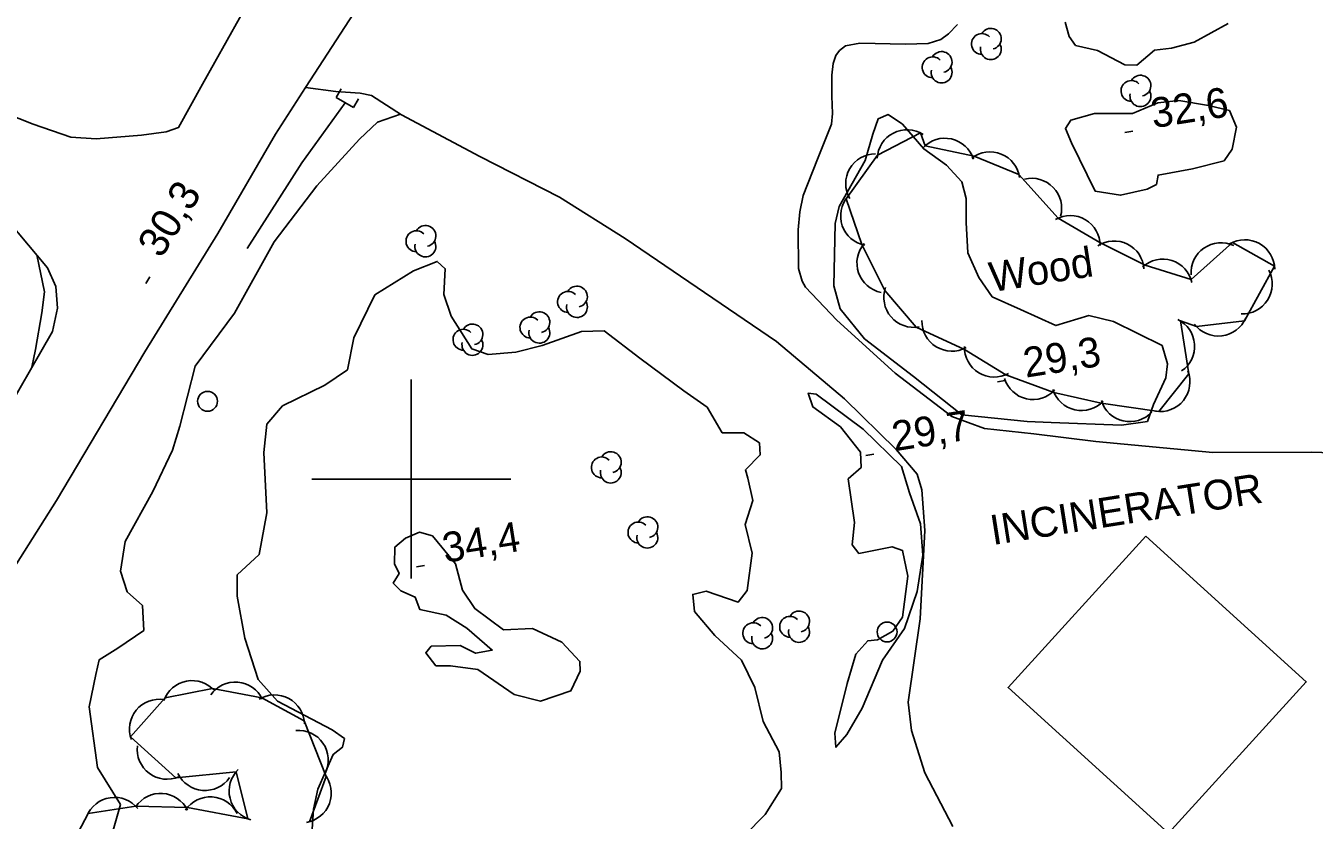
# Model space of a CAD drawing. Extents: x 646142 to 649934, y 5874075 to 5876351.
# Drawn here: x 648161.2 to 648290.8, y 5875365.7 to 5875445.6 of the extents above; entities that cross this region are included whole.
import ezdxf

# ---------------------------------------------------------------- set-up
doc = ezdxf.new("R2010")
doc.units = 0
for name, color, linetype in [('Niveau 1', 7, 'Continuous'), ('Niveau 19', 7, 'Continuous'), ('Niveau 2', 7, 'Continuous'), ('Niveau 21', 7, 'Continuous'), ('Niveau 26', 7, 'Continuous'), ('Niveau 3', 7, 'Continuous'), ('Niveau 31', 7, 'Continuous'), ('Niveau 36', 7, 'Continuous'), ('Niveau 4', 7, 'Continuous'), ('Niveau 44', 7, 'Continuous'), ('Niveau 61', 7, 'Continuous')]:
    doc.layers.add(name, color=color, linetype=linetype)

msp = doc.modelspace()

# ---------------------------------------------------------------- linework, layer by layer
at = {"layer": 'Niveau 1'}
for points in [[(648198.91, 5875436.7), (648196.61, 5875435.88), (648194.79, 5875434.19), (648190.5, 5875429.47), (648186.22, 5875423.84), (648182.23, 5875416.67), (648178.28, 5875411.35), (648176.73, 5875405.31), (648175.99, 5875402.89)], [(648261.93, 5875405.79), (648255.36, 5875406.46), (648250.49, 5875410.31), (648245.57, 5875414.11), (648243.11, 5875417.13), (648242.47, 5875419.43), (648242.63, 5875425.7), (648243.02, 5875427.4), (648245.65, 5875432.04), (648246.42, 5875434.68), (648246.94, 5875436.22), (648247.94, 5875436.64), (648249.38, 5875435.67), (648251.52, 5875433.2), (648253.82, 5875431.55), (648255.37, 5875429.89), (648255.78, 5875428.2), (648255.79, 5875425.79), (648255.96, 5875422.76), (648257.07, 5875420.27), (648258.42, 5875418.31), (648261.26, 5875417.05), (648264.81, 5875415.44), (648268.11, 5875416.45), (648270.62, 5875415.85), (648275.49, 5875413.43), (648276.03, 5875411.58), (648275.85, 5875410.19), (648274.62, 5875407.51), (648274.01, 5875405.79), (648271.41, 5875405.41), (648264.34, 5875405.7), (648261.93, 5875405.79)], [(648161.85, 5875411.24), (648162.21, 5875413.04), (648162.85, 5875416.71), (648163.14, 5875418.82), (648162.35, 5875422.53)], [(648240.72, 5875408.55), (648245.45, 5875405.02), (648249.28, 5875401.26), (648250.11, 5875398.62), (648251.2, 5875395.5), (648251.44, 5875392.36), (648250.86, 5875388.69), (648249.59, 5875384.97), (648247.37, 5875381.8), (648245.32, 5875376.98), (648243.81, 5875374.33), (648242.7, 5875373.04), (648242.59, 5875374.46), (648243.82, 5875379.45), (648244.69, 5875382.39), (648245.9, 5875383.75), (648246.87, 5875383.83), (648248.41, 5875384.7), (648249.39, 5875386.1), (648249.94, 5875390.23), (648249.4, 5875392.82), (648248.34, 5875393.2), (648245.01, 5875392.52), (648244.32, 5875393.39), (648244.55, 5875395.65), (648243.93, 5875400.02), (648245.22, 5875401.16), (648245.16, 5875402.7), (648243.14, 5875405.24), (648240.36, 5875407.25), (648239.91, 5875408.65), (648240.72, 5875408.55)], [(648160.23, 5875354.13), (648162.44, 5875354.36), (648165.53, 5875356.8), (648167.32, 5875358.21), (648169.56, 5875361.1), (648170.04, 5875364.7), (648170.76, 5875367.29), (648168.47, 5875371.01), (648167.61, 5875377.09), (648168.28, 5875380.36), (648168.63, 5875381.83), (648170.49, 5875383.01), (648173.11, 5875384.78), (648172.98, 5875387.3), (648171.44, 5875388.67), (648170.77, 5875390.74), (648171.23, 5875393.71), (648174.01, 5875398.76), (648175.99, 5875402.89)]]:
    msp.add_lwpolyline(points, dxfattribs=at)
at = {"layer": 'Niveau 19'}
for points in [[(648242.79, 5875415.98), (648239.65, 5875419.29), (648239.3, 5875419.89), (648238.94, 5875421.18), (648238.9, 5875425.05), (648239.06, 5875426.88), (648239.39, 5875428.51), (648240.84, 5875432.16), (648242.24, 5875435.67), (648242.35, 5875436.76), (648242.3, 5875438.5), (648242.29, 5875440.6), (648242.42, 5875441.79), (648242.68, 5875442.6), (648243.05, 5875443.08), (648243.67, 5875443.55), (648245.09, 5875443.82), (648249.68, 5875443.72), (648251.97, 5875443.8), (648253.25, 5875444.21), (648254.02, 5875444.78), (648254.92, 5875445.69)], [(648254.46, 5875365.08), (648251.65, 5875370.47), (648250.3, 5875374.73), (648249.97, 5875377.57), (648251.18, 5875385.94), (648251.65, 5875394.82), (648251.48, 5875397.1), (648251.34, 5875398.93), (648250.88, 5875400.5), (648248.75, 5875402.97), (648243.56, 5875408.06), (648236.71, 5875413.82), (648221.5, 5875424.19), (648214.89, 5875428.36), (648206.91, 5875432.43), (648199.03, 5875436.62), (648196.02, 5875438.56), (648194.85, 5875438.81), (648192.43, 5875438.96), (648189.37, 5875439.36)], [(648242.79, 5875415.98), (648248.64, 5875410.65), (648254.35, 5875406.29), (648257.64, 5875405.07), (648262.6, 5875404.55), (648268.84, 5875403.79), (648280.59, 5875402.68), (648290.54, 5875402.69), (648297.65, 5875402.46)]]:
    msp.add_lwpolyline(points, dxfattribs=at)
at = {"layer": 'Niveau 2'}
for points in [[(648274.72, 5875443.14), (648272.95, 5875441.62), (648271.75, 5875441.64), (648269.01, 5875443.08), (648266.8, 5875443.59), (648266.13, 5875444.51), (648265.74, 5875445.94)], [(648282.12, 5875445.81), (648278.72, 5875443.93), (648276.42, 5875443.34), (648274.72, 5875443.14)], [(648274, 5875429.15), (648271.3, 5875428.53), (648268.76, 5875428.96), (648266.39, 5875433.81), (648265.77, 5875435.25), (648266.33, 5875436.1), (648268.69, 5875436.75), (648272.51, 5875436.77), (648275.06, 5875437.84), (648277.16, 5875438.07), (648280.16, 5875437.56), (648282.26, 5875437.05), (648282.96, 5875435.38), (648282.55, 5875433.17), (648281.72, 5875432.01), (648278.53, 5875431.18), (648275.09, 5875430.56), (648274.93, 5875429.63), (648274, 5875429.15)], [(648189.91, 5875362.79), (648190.17, 5875366.82), (648190.6, 5875368.81), (648192.16, 5875372.32), (648193.08, 5875373.03), (648193.3, 5875373.91), (648192.04, 5875374.78), (648186.55, 5875377.66), (648184.61, 5875379.85), (648183.27, 5875383.99), (648182.49, 5875388.23), (648182.51, 5875390.36), (648184.7, 5875392.43), (648185.47, 5875396.62), (648185.18, 5875402.68), (648185.48, 5875405.52), (648187.06, 5875407.37), (648191.31, 5875409.43), (648193.6, 5875411), (648194.22, 5875414.2), (648196.35, 5875418.51), (648200.23, 5875420.94), (648202.62, 5875421.88), (648203.42, 5875421.14), (648203.27, 5875418.55), (648204.01, 5875416.37), (648206.09, 5875413.1), (648207.73, 5875412.54), (648210.52, 5875412.77), (648213.15, 5875413.44), (648217.11, 5875414.85), (648219.39, 5875414.92), (648222.97, 5875412.17), (648227.4, 5875408.86), (648229.75, 5875407.22), (648231.26, 5875404.64)], [(648231.26, 5875404.64), (648233.43, 5875404.65), (648235, 5875403.63), (648235.09, 5875402.43), (648233.6, 5875400.93), (648233.83, 5875400.09), (648234.35, 5875397.84), (648233.56, 5875395.42), (648234.29, 5875392.56), (648233.77, 5875388.79), (648232.88, 5875387.63), (648229.66, 5875388.74), (648228.31, 5875388.4), (648228.49, 5875386.7), (648230.51, 5875384.28), (648233.21, 5875381.8), (648234.56, 5875379.05), (648235.39, 5875375.62), (648236.99, 5875372.59), (648237.2, 5875370.49), (648237.21, 5875368.88)], [(648203.09, 5875393.16), (648204.44, 5875391.49), (648205.16, 5875388.83), (648206.38, 5875386.98), (648209.29, 5875384.84), (648212.19, 5875384.96), (648215.15, 5875383.6), (648216.95, 5875381.66), (648216.97, 5875380.68), (648216.06, 5875378.72), (648213, 5875377.67), (648210.35, 5875378.34), (648206.7, 5875380.85), (648203.93, 5875381.23), (648202.48, 5875381.22), (648201.46, 5875382.52), (648202.01, 5875383.19), (648204.92, 5875383.28), (648206.46, 5875382.49), (648208.15, 5875382.8), (648205.59, 5875385), (648203.52, 5875386.32), (648200.85, 5875386.9), (648200.38, 5875388.13), (648198.94, 5875388.75), (648198.19, 5875389.52), (648198.78, 5875390.49), (648198.3, 5875391.48), (648198.35, 5875393.17), (648199.42, 5875394.06), (648200.83, 5875394.66), (648202.12, 5875394.28), (648203.09, 5875393.16)], [(648237.21, 5875368.88), (648235.58, 5875366.28), (648233.51, 5875364.16)]]:
    msp.add_lwpolyline(points, dxfattribs=at)
at = {"layer": 'Niveau 21'}
for points in [[(648099.75, 5875533.54), (648104.15, 5875520.89), (648107.21, 5875510.79), (648110.53, 5875500.24), (648114.46, 5875487.79), (648117.95, 5875478.06), (648120.06, 5875472.94), (648122.93, 5875466.74), (648127.78, 5875458.84), (648129.46, 5875456.33), (648131.02, 5875453.93), (648135.61, 5875449.35), (648144.82, 5875441.36), (648152.16, 5875433.78), (648158.52, 5875427.05), (648163.43, 5875421.24), (648164.26, 5875419.36), (648164.43, 5875417.18), (648163.92, 5875414.84), (648158.44, 5875405.32)], [(648156.25, 5875385.1), (648164.35, 5875397.84), (648173.2, 5875412.81), (648180.57, 5875424.68), (648186.35, 5875434.69), (648189.37, 5875439.36), (648195.09, 5875448.23), (648197.23, 5875451.55), (648203.19, 5875462.26), (648209.61, 5875472.9), (648210.95, 5875475.33), (648215.36, 5875483.37), (648215.93, 5875484.44), (648222.29, 5875496.47), (648230.28, 5875509.19), (648237.47, 5875521.85), (648244.6, 5875533.81)], [(648233.33, 5875531.95), (648226.44, 5875519.89), (648221.24, 5875511.19), (648211.48, 5875494.64), (648203.63, 5875481.47), (648194.03, 5875465.86), (648185.72, 5875451.61), (648183.97, 5875448.6), (648179.02, 5875439.69), (648176.6, 5875435.35), (648175.37, 5875434.91), (648172.87, 5875434.59), (648168.31, 5875434.22), (648165.77, 5875434.36), (648162, 5875435.67), (648157.63, 5875437.39)]]:
    msp.add_lwpolyline(points, dxfattribs=at)
at = {"layer": 'Niveau 26'}
for p, q in [((648192.45, 5875438.35), (648192.94, 5875439.22)), ((648194.2, 5875437.35), (648192.45, 5875438.35)), ((648194.2, 5875437.35), (648194.7, 5875438.22))]:
    msp.add_line(p, q, dxfattribs=at)
at = {"layer": 'Niveau 3'}
for p, q in [((648271.76, 5875434.86), (648272.55, 5875434.98)), ((648173.3, 5875419.66), (648173.72, 5875420.34)), ((648258.93, 5875409.78), (648259.72, 5875409.9)), ((648245.71, 5875402.38), (648246.5, 5875402.51)), ((648200.54, 5875391.17), (648201.33, 5875391.3))]:
    msp.add_line(p, q, dxfattribs=at)
at = {"layer": 'Niveau 31'}
msp.add_lwpolyline([(648273.85, 5875394.27), (648289.98, 5875379.6), (648276.13, 5875364.39), (648260.01, 5875379.06), (648273.85, 5875394.27)], dxfattribs=at)
at = {"layer": 'Niveau 36'}
for centre in [(648179.52, 5875407.82), (648247.84, 5875384.63)]:
    msp.add_circle(centre, 1, dxfattribs=at)
at = {"layer": 'Niveau 4'}
msp.add_lwpolyline([(648183.51, 5875423.17), (648189.01, 5875431.8), (648193.34, 5875437.84)], dxfattribs=at)
at = {"layer": 'Niveau 44'}
for points in [[(648251.19, 5875434.81), (648246.88, 5875432.58), (648243.71, 5875428.16), (648245.3, 5875423.58), (648247.61, 5875418.96), (648250.75, 5875415.26), (648255.62, 5875413.02), (648259.77, 5875410.49), (648264.62, 5875408.71), (648269.35, 5875407.63), (648275.15, 5875406.78), (648278.19, 5875410.57), (648277.34, 5875415.91), (648278.95, 5875415.35), (648283.77, 5875415.92), (648286.79, 5875421.41), (648282.56, 5875423.78), (648278.41, 5875420.06), (648273.78, 5875421.52), (648269.24, 5875423.78), (648265.05, 5875426.23), (648261.1, 5875430.62), (648256.61, 5875432.45), (648251.68, 5875433.52), (648251.19, 5875434.81)], [(648189.76, 5875365.55), (648191.46, 5875370.09), (648189.23, 5875375.7), (648184.97, 5875378.01), (648180.03, 5875378.93), (648175.26, 5875378.02), (648171.77, 5875374.1), (648176.33, 5875369.95), (648182.39, 5875370.56)], [(648182.39, 5875370.56), (648183.56, 5875365.85), (648177.49, 5875366.98), (648172.31, 5875367.1), (648167.51, 5875366.39), (648164.87, 5875361.34)]]:
    msp.add_lwpolyline(points, dxfattribs=at)
for centre, radius, start, end in [((648258.27, 5875444.27), 1.05, 282.2692, 149.7263), ((648257.37, 5875443.74), 1.05, 44.1154, 269.804), ((648258.27, 5875443.22), 1.05, 166.9369, 29.6212), ((648252.42, 5875441.4), 1.05, 44.1154, 269.804), ((648253.32, 5875441.93), 1.05, 282.2692, 149.7263), ((648253.32, 5875440.88), 1.05, 166.9369, 29.6212), ((648272.41, 5875439.02), 1.05, 44.1154, 269.804), ((648273.31, 5875439.55), 1.05, 282.2692, 149.7263), ((648273.31, 5875438.5), 1.05, 166.9369, 29.6212), ((648249.85, 5875432.13), 3, 57.4061, 177.384), ((648253.66, 5875431.27), 3, 17.2725, 137.2504), ((648246.68, 5875429.71), 3, 89.9936, 209.9715), ((648258.19, 5875429.9), 3, 7.8434, 127.8214), ((648262.39, 5875427.24), 3, 344.1765, 104.1545), ((648246.17, 5875426.45), 3, 139.1316, 259.1095), ((648266.26, 5875423.49), 3, 359.6846, 119.6625), ((648200.52, 5875423.91), 1.05, 44.1154, 269.804), ((648201.42, 5875424.44), 1.05, 282.2692, 149.7263), ((648201.42, 5875423.39), 1.05, 166.9369, 29.6212), ((648247.81, 5875421.72), 3, 139.1316, 259.1095), ((648270.67, 5875420.94), 3, 3.5247, 123.5027), ((648281.4, 5875420.76), 3, 64.623, 184.6009), ((648283.81, 5875421.06), 3, 0.7762, 120.7541), ((648275.56, 5875419.11), 3, 12.4786, 132.4566), ((648283.56, 5875419.61), 3, 267.657, 27.6349), ((648216.66, 5875418.35), 1.05, 282.2692, 149.7263), ((648250.52, 5875418.25), 3, 160.3885, 280.3664), ((648215.76, 5875417.82), 1.05, 44.1154, 269.804), ((648212.88, 5875415.77), 1.05, 282.2692, 149.7263), ((648216.66, 5875417.3), 1.05, 166.9369, 29.6212), ((648206.15, 5875414.54), 1.05, 282.2692, 149.7263), ((648211.98, 5875415.24), 1.05, 44.1154, 269.804), ((648212.88, 5875414.72), 1.05, 166.9369, 29.6212), ((648254.34, 5875415.86), 3, 178.7121, 298.6901), ((648275.76, 5875413.35), 3, 304.3205, 64.2985), ((648281.15, 5875417.38), 3, 216.712, 336.6899), ((648205.25, 5875414.01), 1.05, 44.1154, 269.804), ((648206.15, 5875413.49), 1.05, 166.9369, 29.6212), ((648258.61, 5875413.26), 3, 178.7121, 298.6901), ((648262.51, 5875411), 3, 197.1192, 317.0972), ((648275.29, 5875409.78), 3, 261.3034, 21.2813), ((648267.38, 5875409.89), 3, 197.1192, 317.0972), ((648272.25, 5875408.77), 3, 197.1192, 317.0972), ((648220.06, 5875401.7), 1.05, 282.2692, 149.7263), ((648219.16, 5875401.17), 1.05, 44.1154, 269.804), ((648220.06, 5875400.65), 1.05, 166.9369, 29.6212), ((648223.74, 5875395.16), 1.05, 282.2692, 149.7263), ((648222.84, 5875394.63), 1.05, 44.1154, 269.804), ((648223.74, 5875394.11), 1.05, 166.9369, 29.6212), ((648234.38, 5875384.5), 1.05, 44.1154, 269.804), ((648235.28, 5875385.03), 1.05, 282.2692, 149.7263), ((648238.09, 5875385.15), 1.05, 44.1154, 269.804), ((648238.99, 5875385.68), 1.05, 282.2692, 149.7263), ((648235.28, 5875383.98), 1.05, 166.9369, 29.6212), ((648238.99, 5875384.63), 1.05, 166.9369, 29.6212), ((648177.97, 5875376.74), 3, 40.7575, 160.7354), ((648182.31, 5875376.59), 3, 25.1299, 145.1078), ((648174.67, 5875374.87), 3, 80.8664, 200.8444), ((648186.26, 5875375.3), 3, 1.5005, 121.4784), ((648188.66, 5875371.74), 3, 334.7822, 94.7602), ((648175.45, 5875372.82), 3, 173.0642, 293.0421), ((648179.26, 5875371.69), 3, 205.3657, 325.3436), ((648184.69, 5875368.63), 3, 133.9785, 253.9564), ((648188.96, 5875368.44), 3, 279.5352, 39.5131), ((648170.17, 5875365), 3, 38.4319, 158.4098), ((648174.8, 5875365.4), 3, 26.0862, 146.0642), ((648179.79, 5875365.05), 3, 26.0862, 146.0642)]:
    msp.add_arc(centre, radius, start, end, dxfattribs=at)
at = {"layer": 'Niveau 61'}
for points in [[(648200, 5875410), (648200, 5875400), (648200, 5875390)], [(648190, 5875400), (648200, 5875400), (648210, 5875400)]]:
    msp.add_lwpolyline(points, dxfattribs=at)

# ---------------------------------------------------------------- texts
at = {"layer": 'Niveau 3'}
for s, rotation, p in [('32,6 ', 8.9405, (648274.61, 5875435.27)), ('30,3 ', 58.0527, (648174.86, 5875422.09)), ('29,3 ', 8.9405, (648261.78, 5875410.19)), ('29,7 ', 8.9405, (648248.57, 5875402.79)), ('34,4 ', 8.9405, (648203.39, 5875391.58))]:
    msp.add_text(s, height=3, rotation=rotation, dxfattribs=at).set_placement(p)
at = {"layer": 'Niveau 31'}
msp.add_text('INCINERATOR', height=3, rotation=8.941, dxfattribs=at).set_placement((648258.46, 5875393.36))
at = {"layer": 'Niveau 44'}
msp.add_text('Wood', height=3, rotation=8.9405, dxfattribs=at).set_placement((648258.37, 5875418.79))

doc.saveas('drawing.dxf')
